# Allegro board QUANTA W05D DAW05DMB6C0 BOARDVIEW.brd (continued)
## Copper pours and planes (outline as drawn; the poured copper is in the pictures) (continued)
51216SW on BOTTOM (solid shape): 30.35,23.22 30.35,15.6 30.34,15.59 30.34,14.85 29.82,14.33 28.85,14.33 28.22,14.97 26.66,14.97 26.28,15.35 26.28,15.88 26.94,16.54 26.94,17.53 26.82,17.65 25.12,17.65 25.01,17.76 25.01,20.05 24.88,20.17 23.94,20.17 23.66,20.45 23.66,23.58 23.82,23.73 29.84,23.73
81101_BST on BOTTOM (solid shape): 59.78,108.13 59.82,108.11 59.83,108.08 59.83,107.45 58.95,106.56 56.23,106.56 56.13,106.66 56.13,107.45 56.2,107.52 57.17,107.52 57.32,107.37 58.56,107.37 58.87,107.68 58.87,108.08 58.88,108.11 58.92,108.13
81101_HG_G on BOTTOM (solid shape): 47.64,103.79 48.25,103.79 48.33,103.71 48.33,103 48.3,102.98 46.73,102.98 46.25,103.46 46.25,104.12 46.27,104.15 47.29,104.15
81101_LG on BOTTOM (solid shape): 48.23,110.19 48.23,108.92 48.13,108.82 46.47,108.82 46.27,109.02 46.27,110.09 46.47,110.29 48.13,110.29
81101_LG on IN2 (solid shape): 49.71,109.16 49.71,108.3 49.6,108.18 47.11,108.18 46.93,108.36 46.93,109.28 47.08,109.43 49.45,109.43
81101_LG on IN2 (solid shape): 58.74,110.04 58.74,109.5 58.62,109.38 58.39,109.38 58.34,109.43 57.7,109.43 57.52,109.45 57.34,109.4 57.14,109.4 56.76,109.02 56.15,109.02 56.02,109.15 56.02,109.81 56.51,110.29 58.49,110.29
81101_PH on BOTTOM (solid shape): 42.31,108.21 46.88,108.21 47.36,108.69 48.25,108.69 48.38,108.56 48.38,107.93 48.28,107.83 47.9,107.83 47.49,107.42 47.49,106.63 46.91,106.05 42.92,106.05 42.38,105.52 39.62,105.52 38.73,106.41 38.73,107.26 38.74,107.29 38.78,107.31 38.79,107.31 38.79,108.04 38.78,108.04 38.74,108.06 38.73,108.1 38.73,109.1 39.08,109.45 41.06,109.45
81101_PH on BOTTOM (solid shape): 56.9,109.07 56.94,109.06 56.96,109.02 57.21,108.63 57.68,108.7 57.71,108.71 57.74,108.7 57.88,108.62 58.04,108.59 58.13,108.53 58.11,108.42 57.8,108.11 56.2,108.11 56.13,108.18 56.13,108.95 56.25,109.07
81181_AGND on BOTTOM (solid shape): 67.18,103.48 67.18,103.23 67.09,103.14 65.87,103.14 65.84,103.17 65.64,103.17 65.32,103.48 65.32,103.82 65.5,103.99 66.67,103.99
81181_AGND on IN2 (solid shape): outline of 141 points within 57.9,103.36 67.38,116.29
+BATCHG on BOTTOM (solid shape): outline of 200 points within 146.04,74.26 189.48,96.63
+LCDVCC on BOTTOM (solid shape): 12.64,100.03 12.64,97.54 12.31,97.21 11.37,97.21 11.32,97.24 11.26,97.25 10.82,97.69 10.53,97.69 10.5,97.71 10.48,97.75 10.48,98.99 10.66,99.17 10.96,99.17 11.09,99.29 11.09,100.03 11.27,100.21 12.46,100.21
+PCH_VCCDSW on TOP (solid shape): outline of 506 points within 50.18,66.45 54.27,73.61
+PRWSRC on TOP (solid shape): outline of 403 points within 155.06,89.77 183.51,99.55
+PRWSRC on BOTTOM (solid shape): 187.17,101.98 187.18,101.97 187.18,101.95 187.18,101.32 187.19,101.32 187.19,99.17 187.7,98.66 187.7,97.52 187.57,97.39 183.96,97.39 183.2,96.63 181.35,96.63 180.84,97.13 180.84,97.77 180.78,97.83 180.76,97.83 180.73,97.87 180.23,97.87 180.08,98.02 180.08,101 181.17,102.09 187.06,102.09
+PRWSRC on BOTTOM (solid shape): 161.16,94.47 161.16,90.85 161.14,90.83 161.14,89.72 160.6,89.18 160.06,89.18 159.5,88.63 159.5,88.12 159.38,87.99 158.56,87.99 158.56,88.91 158.21,89.26 154.93,89.26 153.34,87.67 148.14,87.67 147.95,87.86 147.95,89.51 148.07,89.64 149.6,89.64 150.11,90.15 153.15,90.15 153.79,90.78 153.79,92.18 153.28,92.69 153.28,93.45 153.41,93.58 154.17,93.58 154.42,93.32 157.09,93.32 158.49,94.72 160.9,94.72
+SMDDR_VREF_DIMM on BOTTOM (solid shape): 46.52,27.15 46.97,27.15 47.03,27.08 47.03,26.57 46.68,26.22 46.68,25.41 46.58,25.3 45.83,25.3 45.72,25.41 45.72,27.1 45.64,27.19 45.64,27.51 45.72,27.6 46.07,27.6
+SMDDR_VREF_DQ1 on BOTTOM (solid shape): 12.65,65.35 12.65,64.59 12.96,64.29 12.96,63.11 13.23,62.84 13.23,62.49 12.82,62.08 12.44,62.08 12.31,62.21 12.31,63.23 11.7,63.84 11.7,65.46 11.78,65.54 12.46,65.54
+VAD on TOP (solid shape): outline of 3537 points within 148.2,89.67 246.58,112.76
+VAD on BOTTOM (solid shape): 161.03,104.63 161.03,103.1 161.41,102.72 163.44,102.72 163.57,102.6 163.57,95.61 163.44,95.48 157.35,95.48 157.09,95.74 157.09,100.44 156.84,100.69 156.2,100.69 156.08,100.82 156.08,101.45 157.6,102.98 157.6,104.88 157.73,105.01 160.65,105.01
+VAD on BOTTOM (solid shape): 152.91,92.17 152.91,91.81 152.77,91.67 151.88,91.67 151.76,91.55 151.76,90.66 151.5,90.4 149.98,90.4 149.47,89.9 146.93,89.9 146.8,90.02 146.8,90.94 146.27,91.47 146.27,91.72 146.37,91.83 147.41,91.83 147.63,91.61 147.63,91.36 147.79,91.19 149.19,91.19 149.47,91.47 149.47,92.18 149.6,92.31 152.77,92.31
+VAD on BOTTOM (solid shape): 242.18,92.56 242.18,90.53 243.38,89.34 243.38,87.76 243.36,87.74 243.15,87.74 243.12,87.77 243.12,89.02 243.12,89.05 243.1,89.08 242.91,89.08 242.87,89.04 242.87,87.76 242.85,87.74 242.66,87.74 242.62,87.78 242.62,89.05 242.6,89.08 242.41,89.08 242.38,89.05 242.38,87.75 242.36,87.74 242.15,87.74 242.12,87.77 242.12,89.05 242.09,89.08 241.91,89.08 241.88,89.05 241.88,87.78 241.83,87.74 241.66,87.74 241.63,87.77 241.63,89.05 241.6,89.08 241.41,89.08 241.37,89.04 241.37,87.77 241.34,87.74 241.16,87.74 241.13,87.77 241.13,89.05 241.1,89.07 240.91,89.07 240.88,89.04 240.88,87.76 240.86,87.74 240.66,87.74 238.12,90.28 238.12,92.69 238.24,92.82 241.93,92.82
BATT+ on BOTTOM (solid shape): 157.2,88.52 157.21,88.49 157.19,88.44 157.19,88.4 157.18,88.3 157.18,88.24 157.18,87.93 157.22,87.89 157.22,85.25 157.2,85.21 157.17,85.2 146.22,85.2 146.18,85.21 146.17,85.25 146.17,86.34 146.75,86.92 146.77,86.93 146.78,86.92 147.11,87.05 147.24,87.38 147.23,87.39 147.24,87.41 147.31,87.48 153.54,87.48 154.93,88.88 156.84,88.88
BQB_2 on BOTTOM (solid shape): 172.33,101.45 172.33,100.36 172.27,100.3 172.27,99.96 172.33,99.91 172.33,99.75 171.54,98.96 171.54,98.63 171.32,98.4 170.12,98.4 170.1,98.43 170.1,98.63 170.12,98.66 170.91,98.66 171.06,98.81 171.06,99.42 171.39,99.75 171.39,101.53 171.44,101.58 172.2,101.58
BQHIDRV on BOTTOM (solid shape): 172.97,99.56 172.97,99.17 171.7,97.9 170.12,97.9 170.1,97.92 170.1,98.13 170.12,98.15 171.32,98.15 171.72,98.56 171.72,98.86 172.54,99.68 172.84,99.68
BQHIDRV on BOTTOM (solid shape): 182.03,108.56 182.03,107.88 181.81,107.65 181.68,107.65 181.65,107.68 181.64,107.64 181.6,107.63 180.89,107.63 180.87,107.65 180.87,107.98 181.17,107.98 181.4,108.21 181.4,108.48 181.63,108.7 181.89,108.7
BQLODRV on TOP (solid shape): 171.18,101.55 171.18,100.69 170.75,100.26 169.84,100.26 169.57,100.53 169.57,101.67 169.68,101.78 170.95,101.78
BQLODRV on TOP (solid shape): 181.25,108.92 181.25,108.39 180.74,107.88 180.74,107.7 180.46,107.42 179.57,107.42 179.44,107.55 179.44,108.06 180.52,109.14 181.03,109.14
BQLODRV on BOTTOM (solid shape): 170.17,101.31 170.17,99.52 169.99,99.34 169.69,99.34 169.64,99.4 169.64,101.43 169.74,101.53 169.96,101.53
BQLODRV on BOTTOM (solid shape): 181.09,109.48 181.09,108.97 181.27,108.79 181.27,108.46 181.02,108.21 180.79,108.21 180.56,107.98 180.26,107.98 180.22,108.02 180.22,108.5 179.72,109 179.72,109.81 180.76,109.81
BQLR on BOTTOM (solid shape): 179.82,100.18 179.82,96.89 179.96,96.75 179.96,96 179.74,95.78 178.14,95.78 178.05,95.86 178.05,97.13 177.67,97.52 176.52,97.52 176.52,97.8 176.27,98.05 176.27,99.93 176.78,100.44 179.57,100.44
BQPHASE on BOTTOM (solid shape): 173.73,99.04 173.73,98.15 172.64,97.06 171.62,97.06 171.29,97.39 170.15,97.39 170.1,97.44 170.1,97.64 170.12,97.67 171.52,97.67 171.72,97.67 172.31,98.25 172.33,98.25 173.25,99.17 173.6,99.17
BQPHASE on BOTTOM (solid shape): 180.05,108.29 180.05,107.35 180.13,107.27 181.58,107.27 181.63,107.22 181.63,105.03 179.06,102.47 175.51,102.47 175.05,102.93 175.05,106.36 175.72,107.03 176.84,107.03 177.12,107.31 177.12,107.61 177.69,108.18 177.69,108.36 177.72,108.39 179.95,108.39
CPVSS on SGND (solid shape): 213.35,84.33 213.35,83.65 215.13,81.87 215.13,78.97 214.24,78.97 213.86,78.59 213.86,77.83 213.56,77.61 213.6,77.24 213.56,77.2 212.99,77.2 212.36,76.56 210.66,76.56 210.56,76.67 210.56,77.81 210.16,78.21 209.77,78.21 209.67,78.32 209.67,81.03 210.21,81.56 211.7,81.56 212.59,82.45 212.59,83.85 212.46,83.98 212.46,84.33 212.56,84.43 213.25,84.43
CPVSS on SVCC (solid shape): 213.35,84.33 213.35,83.65 215.13,81.87 215.13,78.97 214.24,78.97 213.86,78.59 213.86,77.86 213.54,77.62 213.56,77.23 213.53,77.2 212.99,77.2 212.36,76.56 210.66,76.56 210.56,76.67 210.56,77.76 210.1,78.21 209.77,78.21 209.67,78.32 209.67,81.03 210.21,81.56 211.68,81.56 212.59,82.48 212.59,83.77 212.46,83.9 212.46,84.33 212.56,84.43 213.25,84.43
NB670BST on BOTTOM (solid shape): 101.01,111.64 101.01,110.17 101.35,109.82 101.35,109.01 101.34,109 100.93,109 100.21,109.72 100.21,111.66 100.26,111.71 100.93,111.71
NB670SW on BOTTOM (solid shape): 99.74,111.51 99.74,108.84 99.94,108.64 102.25,108.64 102.43,108.46 102.43,108.1 102.42,108.07 102.41,108.05 102.38,108.04 101.72,108.04 101.72,107.55 102.38,107.55 102.41,107.54 102.42,107.52 102.43,107.42 102.3,107.29 100.4,107.29 100.23,107.13 98.33,107.13 97.78,106.58 97.78,104.68 97.6,104.5 96.82,104.5 96.72,104.6 96.72,106.58 96,107.29 96,107.46 101.45,107.46 101.45,108.05 100.25,108.05 100.25,107.46 96,107.46 96,110.7 96.92,111.61 99.64,111.61
NB671BST on BOTTOM (solid shape): 153.87,106.1 153.87,105.36 153.84,105.34 153.04,105.34 152.76,105.05 152.32,105.05 152.04,105.34 151.41,105.34 151.38,105.35 151.36,105.39 151.36,106.15 151.38,106.19 151.41,106.2 153.76,106.2
NB671SW on BOTTOM (solid shape): 162.68,112.88 162.68,109.83 162.17,109.33 157.17,109.33 155.9,108.06 153.15,108.06 152.9,107.8 152.9,106.74 152.77,106.61 150.41,106.61 150.28,106.74 150.28,107.13 150.29,107.16 150.3,107.17 152.46,107.17 152.46,107.77 151.27,107.77 151.27,107.17 150.3,107.17 150.33,107.18 151,107.18 151,107.68 150.33,107.68 150.31,107.69 150.29,107.7 150.28,107.73 150.28,107.96 150.35,108.02 152.02,108.02 152.29,108.29 152.29,109.35 152.93,109.99 154.35,109.99 155.01,110.65 155.77,110.65 155.86,110.74 155.86,112.79 156.46,113.39 162.17,113.39
N17058778 on BOTTOM (solid shape): 202.58,81.87 204.64,81.87 204.74,81.77 204.74,81.07 204.7,81.03 204.18,81.03 204.03,80.88 204.03,80.37 204,80.35 203.98,80.34 203.29,80.34 203.27,80.34 203.22,80.4 203.22,80.68 203.09,80.8 201.31,80.8 201.16,80.96 201.16,82.1 201.26,82.2 202.25,82.2
N21954661 on BOTTOM (solid shape): 74.88,85.45 74.96,85.43 75.03,85.42 75.1,85.43 75.18,85.45 75.54,85.45 75.57,85.43 75.57,85.19 75.55,85.15 75.52,85.13 74.99,85.13 73.47,83.62 72.29,83.62 72.26,83.64 72.24,83.67 72.24,84.91 72.28,84.94 72.59,84.94 73.09,85.45
N41545080 on BOTTOM (solid shape): 127.32,108.77 128.19,108.77 128.57,108.39 128.57,106.1 128.5,106.04 126.5,106.04 126.41,106.13 126.41,107.65 126.62,107.87 126.62,108.76 126.66,108.79 127.3,108.79

Small or netless copper shapes (teardrops, artwork), in the pictures only: 1 on TOP, 13 on BOTTOM, 83 on IN2

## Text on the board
Ref Des/Silkscreen Bottom: D | F | C | E | O | G | B | M | I | A | N | K | AB | L | P | R | H | Q | U | T | Y | J | AL | AG | AJ | AI | AK | AH | AA | AD | Z | AC | AF | AE | W | V | X | MODEL:W05D | DAW05DMB6C0 REV:C
User.Comments: 15.0x24.0 | 16.0x79.0 | 120.5 | 289.7
Ref Des/Silkscreen Top: DAW05DMB6C0 REV:C
User.21: Limit
User.25: W05D-MB | DATE | 03/07/13' | PROJECT | LAYER | REV. | TOP | A | 1 | DAW05DMB6A0 | 16.5
User.26: W05D-MB | DATE | 03/07/13' | PROJECT | LAYER | REV. | SGND | A | 2 | DAW05DMB6A0 | 16.5
User.27: W05D-MB | DATE | 03/07/13' | PROJECT | LAYER | REV. | IN1 | A | 3 | DAW05DMB6A0 | 16.5
User.28: W05D-MB | DATE | 03/07/13' | PROJECT | LAYER | REV. | IN2 | A | 4 | DAW05DMB6A0 | 16.5
User.29: W05D-MB | DATE | 03/07/13' | PROJECT | LAYER | REV. | SVCC | A | 5 | DAW05DMB6A0 | 16.5
User.30: W05D-MB | DATE | 03/07/13' | PROJECT | LAYER | REV. | A | 6 | BOTTOM | DAW05DMB6A0 | 16.5
User.31: TP61 | TP41 | TP47 | TP50 | TP53 | TP54 | TP56 | TP58 | TP60 | TP62 | TP36 | TP42 | TP28 | TP24 | TP46 | TP33 | TP27 | TP15 | TP19 | TP21 | TP37 | TP32 | TP31 | TP14 | TP16 | TP26 | TP17 | TP22 | TP23 | TP12 | TP11 | TP57 | TP40 | TP43 | TP49 | TP18 | TP35 | TP45 | TP34 | TP25 | TP39 | TP44 | TP59 | TP51 | TP55 | TP29 | TP13 | TP30 | TP38 | TP48 | TP52 | PD1 | TP63 | TP20 | TP10 | R10 | TP7 | C1 | 14 | 16 | 13 | U2 | 9 | 5 | 6 | 8 | 2 | CN1 | 30 | 7 | U3 | 18 | 60 | 31 | 52 | PC1 | PC2 | PC3 | PC4 | R1 | C2 | U1 | R8 | R9 | R2 | R3 | R5 | R4 | TP6 | TP3 | TP9 | TP1 | TP5 | TP8 | TP2 | TP4 | R11 | CN2 | R6 | R7 | W05D-MB | DATE | 03/07/13' | PROJECT | LAYER | REV. | SK_TOP | A | DAW05DMB6A0 | DAW05DMB6A0 REV:A | 16.5
User.32: H4 | H11 | R416 | R424 | R427 | R429 | R433 | R436 | R437 | PR130 | C360 | C250 | C178 | C183 | C188 | C190 | C198 | C204 | R256 | R262 | EC12 | C88 | C104 | C113 | C122 | C121 | D | PC142 | PC143 | F | C | R342 | C274 | R384 | C277 | EC11 | C276 | R326 | C205 | C219 | R270 | C259 | R328 | R350 | R295 | C282 | PC140 | PR122 | R473 | R278 | TP91 | R301 | PC151 | R323 | R329 | C279 | E | C309 | R343 | R347 | PC137 | R354 | R395 | R361 | PR123 | R159 | R173 | PL15 | H9 | PC82 | C154 | G | B | PQ14 | PC34 | 4 | R417 | PC33 | R370 | R374 | R378 | O | R382 | C21 | R369 | R373 | R377 | C20 | C281 | PQ15 | R196 | PC32 | C358 | R277 | PL14 | R244 | R253 | R258 | R96 | R114 | R121 | PC93 | PC102 | R261 | C235 | R276 | R97 | R118 | R200 | R213 | R243 | R251 | C49 | C62 | C81 | C108 | C132 | PC72 | EC7 | PC148 | M | C306 | PC64 | C48 | C61 | C80 | C107 | C131 | C166 | I | C299 | C305 | PR28 | C47 | C60 | C79 | C106 | C130 | C165 | C286 | C289 | C291 | C46 | C59 | C78 | C105 | C129 | C164 | A | C312 | C63 | C77 | C103 | C127 | EC3 | PC86 | C285 | C288 | R411 | R461 | PC67 | PC40 | C76 | C95 | C124 | C149 | R432 | R434 | R435 | R438 | C290 | C292 | C293 | N | TP100 | TP95 | PC65 | C311 | C323 | R404 | C138 | TP96 | R422 | TP101 | EC5 | PC39 | R403 | R154 | C137 | R181 | K | C310 | R180 | AB | C117 | C151 | C170 | R460 | L | R470 | C118 | R123 | R134 | R150 | R166 | PR3 | C342 | C169 | R459 | H6 | R122 | R133 | R149 | R165 | R177 | P | C116 | C136 | R446 | R447 | R449 | R450 | R452 | PQ5 | R172 | R160 | R148 | C308 | C313 | C324 | C338 | R | R94 | R90 | H | C177 | R405 | C294 | PL9 | Q | R469 | C340 | C341 | Q26 | PC17 | PR5 | PC6 | R379 | R348 | R93 | R365 | R368 | 5 | U | R380 | R392 | PR4 | TP68 | R398 | R453 | R454 | R456 | C120 | PC5 | C162 | C168 | C175 | T | 3 | C50 | R381 | R383 | R385 | R388 | R396 | R321 | C58 | 8 | PC92 | R402 | R169 | C93 | C123 | C135 | R338 | R346 | R353 | R359 | R364 | R324 | U9 | Q24 | C297 | PR75 | R337 | R345 | R352 | R358 | R363 | R390 | R397 | R401 | R415 | R423 | PR97 | EC13 | EC14 | R455 | R451 | C298 | PR8 | H12 | R268 | R320 | R336 | R349 | C275 | R360 | PC94 | R112 | R131 | R325 | PL1 | R235 | H7 | PC9 | PC98 | PQ10 | R298 | R297 | C251 | 15 | PR84 | H2 | PR93 | C203 | PC75 | PC85 | PR92 | C202 | PL3 | PR91 | C186 | Y | PC48 | PR51 | R187 | R205 | PC46 | R288 | R294 | R303 | R313 | C23 | PR72 | PC89 | PR87 | PR99 | PC118 | PC101 | R239 | PR77 | PR65 | PR73 | J | R287 | R293 | R302 | R314 | R33 | PC83 | PC88 | C45 | R273 | R285 | R291 | R61 | PC117 | PC122 | R45 | PC103 | R62 | R69 | R72 | PC87 | PC121 | R242 | R215 | R230 | C233 | C241 | R22 | PC43 | PC12 | PR14 | PC11 | PC14 | C43 | R68 | R71 | R263 | R267 | C237 | R275 | R289 | C255 | PR58 | PL2 | PC30 | PR31 | PR37 | C224 | C228 | C247 | C239 | PR41 | PR45 | PC73 | PR71 | PC31 | PR32 | PC47 | AL | EC9 | PR62 | PR70 | PC125 | PC116 | PC123 | H5 | PR111 | PJP3 | C206 | PQ11 | AG | PR110 | PC35 | C231 | PR112 | C201 | C207 | PL13 | PL12 | R252 | PC79 | AJ | R207 | R206 | R237 | R245 | C179 | C184 | PC124 | R125 | C134 | C155 | R162 | R178 | R186 | AI | AK | R132 | R151 | R161 | R176 | R130 | R138 | R147 | R163 | R183 | R192 | C263 | C271 | R340 | R137 | R146 | R167 | R182 | C180 | R317 | C270 | R339 | PL11 | H3 | AH | PC134 | C227 | C232 | C238 | PQ2 | AA | PC38 | R257 | Q20 | AD | PC128 | Z | PC81 | PR102 | PD6 | R197 | R209 | R86 | C40 | C111 | C156 | R101 | C84 | C39 | C67 | R99 | R106 | R111 | R139 | R126 | C83 | AC | R279 | R292 | R296 | C257 | R316 | C273 | AF | AE | R25 | R24 | R330 | R319 | R335 | R318 | R334 | R26 | R341 | R13 | R15 | C18 | R107 | C112 | C119 | R12 | R16 | C194 | Q23 | Q18 | C236 | R30 | C8 | R19 | R21 | R47 | R34 | Q1 | C7 | R221 | H1 | R210 | R14 | R18 | R229 | Q19 | R116 | C125 | R142 | R84 | R92 | C89 | C65 | C187 | C193 | C230 | 20 | 16 | R201 | W | C64 | C74 | R95 | R98 | R105 | R109 | R115 | R119 | C185 | U10 | 11 | 6 | C37 | C38 | R60 | R66 | C52 | C57 | C13 | C17 | C25 | C36 | R20 | R158 | V | 10 | R56 | R58 | R65 | R157 | C53 | Q7 | R156 | Q3 | X | C44 | R67 | Q6 | Q2 | R48 | R52 | R54 | R57 | C19 | R32 | R40 | R46 | R49 | R50 | R53 | R70 | C55 | R73 | R117 | C68 | C73 | C92 | C150 | C157 | C167 | PC147 | C357 | R269 | CN14 | C54 | 2 | CN12 | PR125 | R355 | R387 | C280 | D9 | 17 | U8 | D7 | TP83 | TP94 | U11 | 63 | 62 | 61 | 60 | 59 | 71 | 72 | 58 | 57 | Y4 | 51 | 56 | PR132 | 55 | 73 | TP79 | 74 | C355 | TP78 | TP80 | 50 | 49 | PR29 | C163 | 48 | R265 | 47 | TP82 | 46 | PR40 | 45 | 44 | TP85 | PR126 | 43 | 42 | PL7 | 41 | 40 | PR39 | 39 | U20 | 38 | 37 | 36 | 35 | 34 | 32 | 33 | 31 | 30 | PQ3 | 29 | 28 | 27 | C337 | 26 | PR69 | 25 | 24 | 23 | 21 | 22 | PR38 | 19 | 18 | PC53 | TP74 | 14 | Y2 | 9 | 7 | PR1 | TP76 | L11 | 1 | AY | AN | AR | AV | AU | PU3 | AM | AT | AW | AP | CN13 | PC107 | L10 | RP2 | Q25 | 203 | 204 | RP3 | RP1 | TP90 | PR16 | PU1 | TP70 | C139 | L9 | 12 | R179 | U17 | PR85 | TP66 | PR78 | Y3 | PR50 | PC91 | PC96 | PU6 | PU7 | PD4 | PR86 | R31 | PC18 | PD5 | L16 | L17 | C226 | L13 | C217 | C225 | PR116 | U14 | C229 | PU5 | PR115 | PR88 | L14 | R246 | C218 | PC132 | C248 | C256 | C261 | PQ6 | D6 | CN3 | C126 | C234 | 128 | U19 | U4 | C264 | D3 | C272 | U18 | 97 | 64 | 65 | 96 | R17 | C12 | L1 | CN4 | U12 | CN6 | R259 | U5 | Y1 | U6 | L12 | C27 | D4 | 13 | 54 | 53 | 52 | L5 | C260 | C86 | R308 | R307 | PR128 | PR127 | PR129 | C284 | C295 | C354 | R476 | C353 | C352 | C94 | C283 | PC145 | C351 | R367 | PC150 | R250 | R475 | PC144 | R143 | R366 | C350 | PC149 | R474 | PR131 | C349 | R249 | C348 | R248 | R344 | R129 | R351 | C262 | R91 | C347 | PC138 | EC15 | R128 | PC139 | C258 | R240 | R472 | C109 | R199 | R306 | PR124 | R127 | R198 | PC152 | R191 | C359 | R362 | R190 | R394 | R189 | C35 | PC71 | R188 | R393 | EC8 | R175 | TP87 | R389 | C278 | R386 | C304 | R372 | R371 | C303 | EC1 | R266 | C302 | TP67 | EC6 | C301 | PR64 | C300 | PR61 | PR60 | PJP4 | PR57 | PR56 | Q27 | R55 | PR55 | PR54 | C318 | PR53 | C317 | PR52 | C316 | R168 | EC2 | C315 | R412 | R421 | PC74 | R171 | R420 | R170 | R419 | C174 | R418 | C314 | C173 | R410 | PC66 | C172 | R409 | C171 | PC90 | R164 | C287 | R174 | PR11 | R82 | PR17 | PL8 | R465 | R81 | PC27 | PR15 | C71 | R464 | R85 | R463 | R407 | R426 | C70 | R406 | R425 | R428 | C82 | C85 | PR10 | R458 | PC105 | R466 | C307 | PC104 | R457 | PR2 | R462 | R414 | R471 | R413 | PC70 | R408 | PC69 | PC42 | Q11 | PC63 | PC62 | PC21 | PR6 | C345 | H13 | R357 | C343 | R356 | R300 | C176 | R315 | PL10 | R375 | C100 | R440 | C99 | R333 | R439 | R400 | U16 | R444 | R399 | PR9 | Q21 | R391 | R443 | PR90 | Q10 | R430 | U21 | R264 | R442 | PR89 | R238 | PJP1 | Q22 | R431 | R441 | R445 | R448 | PC20 | C296 | PC100 | R299 | R312 | C153 | PC19 | C152 | R255 | R153 | PC16 | C208 | R141 | R247 | Q17 | R254 | R87 | PC15 | C98 | PC7 | PC112 | PC10 | PJP2 | R241 | U13 | R286 | C115 | U15 | C114 | R284 | PC8 | R113 | C182 | PL5 | PC114 | R195 | PC25 | PC76 | R194 | PC78 | R193 | EC4 | C181 | PC77 | PC80 | C242 | PR68 | R283 | PR67 | R282 | EC10 | PC52 | PC49 | R281 | PC51 | C243 | R280 | R28 | R219 | R27 | R218 | C28 | C14 | C33 | C32 | R274 | C31 | C30 | R204 | PR48 | PD2 | C29 | R203 | PR47 | R37 | PR80 | PC113 | PC120 | R202 | R39 | PC24 | PR46 | PR79 | R208 | R38 | R304 | R214 | C24 | PR24 | R305 | R217 | R36 | PR23 | R309 | R216 | C26 | R272 | R290 | PC23 | R35 | C249 | PR22 | PR100 | PR35 | C16 | C245 | C15 | C244 | PC29 | PU2 | PR83 | PR82 | PC61 | PC59 | PR13 | PR81 | PR20 | PC60 | C253 | PC13 | PR19 | PR94 | PR98 | C252 | PR12 | PC22 | PR44 | PR18 | PC44 | PR34 | R260 | PR33 | PQ4 | PQ8 | C215 | PR114 | C214 | PC111 | PL6 | PC110 | PC56 | PC109 | PC55 | PC108 | PC54 | C221 | PC57 | PR117 | PC95 | PR27 | C209 | PR26 | PR76 | PR25 | H10 | C216 | PQ13 | PC28 | C222 | R234 | C213 | PC50 | PC133 | R233 | C212 | PD3 | R232 | PC97 | C211 | R231 | C210 | C200 | C199 | TP77 | PL4 | TP75 | PQ7 | PR109 | PR108 | PC131 | C265 | PR107 | PR119 | R322 | PR106 | R327 | PR118 | PC136 | PR121 | PR120 | PC135 | PC41 | C161 | C160 | PR103 | C269 | C159 | C268 | C158 | C267 | PQ1 | C266 | PC130 | PC129 | R103 | PR104 | R102 | PC37 | PC119 | R104 | R185 | R100 | PC36 | R184 | C91 | PC127 | C90 | C72 | C97 | R80 | C42 | C96 | R79 | C148 | R78 | PQ9 | R77 | C146 | R76 | R220 | Q16 | R89 | R88 | C246 | R145 | R83 | R144 | R108 | C133 | R332 | R331 | R29 | R23 | C9 | D1 | C22 | C4 | C3 | R310 | H8 | C6 | C5 | C66 | C220 | R212 | R211 | C189 | R236 | C145 | R228 | C144 | C197 | R227 | R226 | C195 | C196 | C192 | R225 | R224 | R51 | R223 | R44 | R222 | R43 | C41 | C34 | C51 | C56 | R42 | R64 | R63 | R136 | R135 | Q4 | Q8 | Q9 | C102 | C143 | C101 | C142 | C141 | C87 | C140 | R120 | R152 | R124 | C128 | R110 | C110 | JDIM1 | C356 | C75 | PC141 | PU8 | L8 | CN7 | C346 | TP81 | R376 | D5 | TP89 | TP84 | TP99 | TP98 | TP97 | TP92 | TP93 | PC146 | RP4 | C322 | C321 | R75 | C336 | C335 | C334 | C320 | C333 | C332 | L7 | C331 | L6 | C330 | C329 | C328 | TP102 | C327 | C326 | R74 | C325 | R468 | R467 | TP103 | TP106 | U22 | TP105 | TP104 | PR36 | C339 | PR74 | C319 | PR66 | C344 | R311 | FAN1 | PR7 | R155 | TP73 | TP71 | R140 | TP69 | TP72 | PC58 | PC99 | PU4 | PR63 | PC84 | Q5 | TP86 | TP88 | PR96 | PR95 | PR21 | PC68 | PR49 | PC115 | R271 | PC45 | PR59 | PC126 | PQ12 | C223 | L15 | PC26 | PR43 | PR113 | PR30 | PC106 | CN9 | PD8 | PR42 | C240 | C254 | PR101 | PR105 | PD7 | Q14 | Q15 | CN8 | C147 | D2 | D8 | U7 | L18 | C10 | TP65 | TP64 | D10 | C191 | R59 | L4 | L3 | R41 | L2 | CN5 | C11 | CN11 | C69 | Q12 | Q13 | CN10 | W05D-MB | DATE | 03/07/13' | PROJECT | LAYER | REV. | SK_BOT | DAW05DMB6A0 | MODEL:W05D | DAW05DMB6A0 REV:A | 16.5
User.45: FIGURE | TYPE | Oblong | Circle | SIZE | 24.0x15.0 | 79.0x16.0 | 10.0 | 12.0 | 14.0 | 91.0 | 138.0 | 142.0 | 28.0 | 40.0 | 43.0 | 63.0 | DRILL CHART: TOP to BOTTOM | ALL UNITS ARE IN MILS | PLATED | NON-PLATED | ROTATION | 0.000 | 90.000 | - | QTY | 26 | 2 | 56 | 2900 | 22 | 309 | 4 | 5 | 1 | 3249 | TOTAL HOLES:
